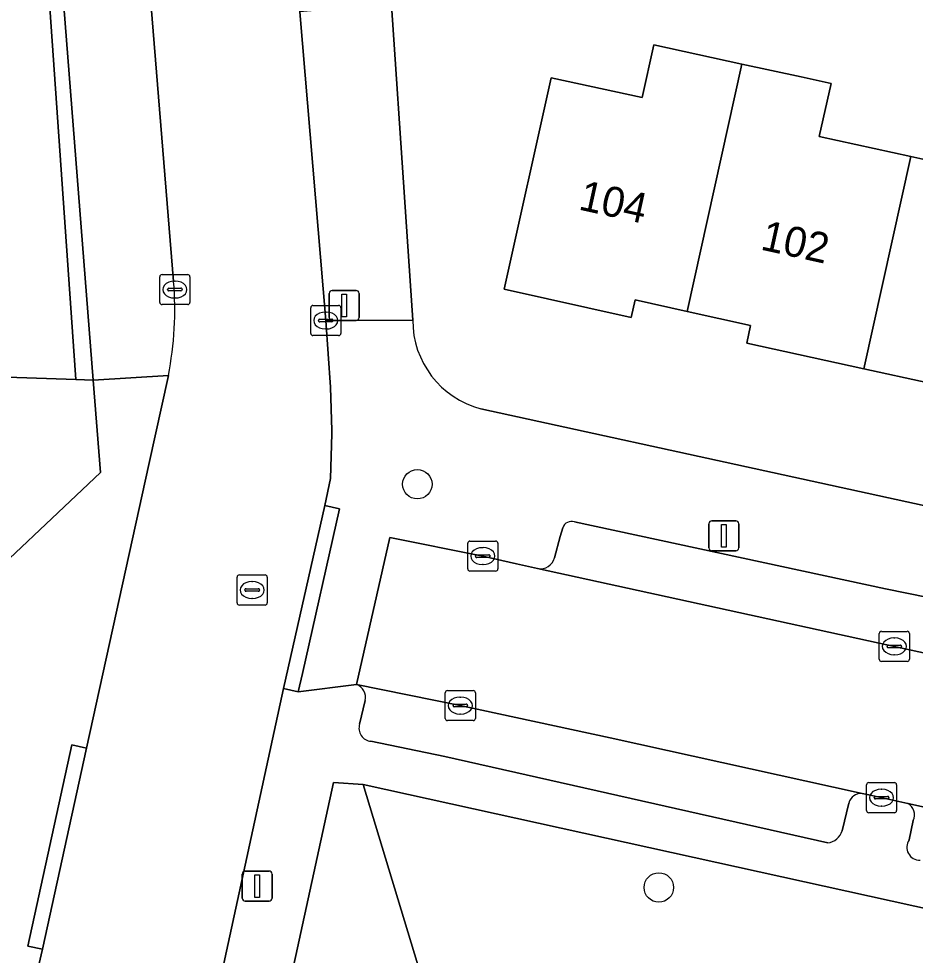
# Model space of a CAD drawing. Extents: x 162172 to 163187, y 382874 to 383685.
# Drawn here: x 162715.37 to 162745.12, y 383152.09 to 383183.19 of the extents above; entities that cross this region are included whole.
import ezdxf

# ---------------------------------------------------------------- set-up
doc = ezdxf.new("R2010")
doc.units = 0
for name, color, linetype in [('IMGEO_Berm_groen', 7, 'Continuous'), ('IMGEO_Boom', 7, 'Continuous'), ('IMGEO_Erf', 7, 'Continuous'), ('IMGEO_Groenvoorziening', 7, 'Continuous'), ('IMGEO_Haag', 7, 'Continuous'), ('IMGEO_Kolk', 7, 'Continuous'), ('IMGEO_Lichtmast', 7, 'Continuous'), ('IMGEO_Pand', 7, 'Continuous'), ('IMGEO_Pand_nummerreeks', 7, 'Continuous'), ('IMGEO_Parkeervlak_open', 7, 'Continuous'), ('IMGEO_Rijbaan_lokaal_open', 7, 'Continuous'), ('IMGEO_Rioolput', 7, 'Continuous'), ('IMGEO_Voetpad_open', 7, 'Continuous')]:
    doc.layers.add(name, color=color, linetype=linetype)

msp = doc.modelspace()

# ---------------------------------------------------------------- linework, layer by layer
at = {"layer": 'IMGEO_Berm_groen'}
msp.add_lwpolyline([(162716.279, 383185.309), (162716.729, 383185.316), (162716.471, 383188.924), (162712.883, 383188.659), (162714.318, 383171.307), (162717.264, 383171.207)], close=True, dxfattribs=at)
at = {"layer": 'IMGEO_Boom'}
for centre in [(162728.595, 383167.73), (162736.61, 383154.34)]:
    msp.add_circle(centre, 0.489, dxfattribs=at)
at = {"layer": 'IMGEO_Erf'}
for points in [[(162747.483, 383189.117), (162743.559, 383188.807), (162742.906, 383183.964), (162740.016, 383184.611), (162737.106, 383185.262), (162737.819, 383188.434), (162727.457, 383187.732), (162728.442, 383173.18)], [(162747.689, 383170.632), (162743.416, 383171.565), (162739.53, 383172.414), (162739.658, 383173), (162737.556, 383173.471), (162735.826, 383173.858), (162735.696, 383173.272), (162731.475, 383174.203), (162733.033, 383181.229), (162736.055, 383180.57), (162736.449, 383182.328)], [(162736.449, 383182.328), (162739.37, 383181.686), (162741.333, 383181.255), (162742.329, 383181.036), (162741.936, 383179.278), (162744.972, 383178.611), (162748.06, 383177.932)], [(162730.7, 383170.234), (162770.835, 383161.462)]]:
    msp.add_lwpolyline(points, dxfattribs=at)
msp.add_arc((162731.489, 383173.177), 3.047, 179.9441, 254.9936, dxfattribs=at)
at = {"layer": 'IMGEO_Groenvoorziening'}
for points in [[(162716.729, 383185.316), (162716.279, 383185.309), (162717.264, 383171.207), (162717.838, 383171.191)], [(162717.838, 383171.191), (162717.264, 383171.207), (162714.318, 383171.307), (162699.343, 383174.603), (162699.21, 383174.01), (162688.833, 383176.346), (162687.285, 383169.49), (162713.429, 383163.736), (162718.079, 383168.119)], [(162729.541, 383148.699), (162726.801, 383157.757), (162725.818, 383157.824), (162723.293, 383146.233), (162728.727, 383145.028)], [(162758.721, 383142.201), (162760.411, 383150.342), (162726.801, 383157.757), (162729.541, 383148.699), (162757.134, 383142.554)]]:
    msp.add_lwpolyline(points, close=True, dxfattribs=at)
at = {"layer": 'IMGEO_Haag'}
msp.add_lwpolyline([(162699.343, 383174.603), (162699.21, 383174.01), (162688.833, 383176.346), (162687.285, 383169.49), (162713.429, 383163.736), (162718.079, 383168.119), (162717.838, 383171.191), (162717.264, 383171.207), (162714.318, 383171.307)], close=True, dxfattribs=at)
at = {"layer": 'IMGEO_Kolk'}
for p, q in [((162720.123, 383174.695), (162720.975, 383174.695)), ((162720.048, 383173.769), (162720.048, 383174.621)), ((162720.536, 383174.475), (162720.561, 383174.475)), ((162721.049, 383174.621), (162721.049, 383173.769)), ((162720.307, 383174.189), (162720.307, 383174.201)), ((162720.745, 383174.152), (162720.347, 383174.152)), ((162720.35, 383174.238), (162720.748, 383174.238)), ((162720.791, 383174.201), (162720.791, 383174.189)), ((162720.559, 383173.915), (162720.534, 383173.915)), ((162720.975, 383173.695), (162720.123, 383173.695)), ((162725.057, 383172.741), (162725.057, 383173.593)), ((162725.132, 383173.667), (162725.984, 383173.667)), ((162725.545, 383173.447), (162725.57, 383173.447)), ((162726.058, 383173.593), (162726.058, 383172.741)), ((162725.316, 383173.161), (162725.316, 383173.173)), ((162725.754, 383173.124), (162725.356, 383173.124)), ((162725.359, 383173.21), (162725.757, 383173.21)), ((162725.8, 383173.173), (162725.8, 383173.161)), ((162725.568, 383172.887), (162725.543, 383172.887)), ((162725.984, 383172.667), (162725.132, 383172.667)), ((162730.268, 383164.918), (162730.268, 383165.77)), ((162730.343, 383165.844), (162731.195, 383165.844)), ((162731.269, 383165.77), (162731.269, 383164.918)), ((162730.527, 383165.338), (162730.527, 383165.35)), ((162730.57, 383165.387), (162730.968, 383165.387)), ((162730.756, 383165.624), (162730.781, 383165.624)), ((162731.011, 383165.35), (162731.011, 383165.338)), ((162730.965, 383165.301), (162730.567, 383165.301)), ((162730.779, 383165.064), (162730.754, 383165.064)), ((162731.195, 383164.844), (162730.343, 383164.844)), ((162744.002, 383162.845), (162744.854, 383162.845)), ((162743.927, 383161.919), (162743.927, 383162.771)), ((162744.415, 383162.625), (162744.44, 383162.625)), ((162744.928, 383162.771), (162744.928, 383161.919)), ((162744.186, 383162.339), (162744.186, 383162.351)), ((162744.624, 383162.302), (162744.226, 383162.302)), ((162744.229, 383162.388), (162744.627, 383162.388)), ((162744.67, 383162.351), (162744.67, 383162.339)), ((162744.438, 383162.065), (162744.413, 383162.065)), ((162744.854, 383161.845), (162744.002, 383161.845)), ((162729.522, 383159.953), (162729.522, 383160.805)), ((162729.597, 383160.879), (162730.449, 383160.879)), ((162730.523, 383160.805), (162730.523, 383159.953)), ((162729.781, 383160.373), (162729.781, 383160.385)), ((162729.824, 383160.422), (162730.222, 383160.422)), ((162730.01, 383160.659), (162730.035, 383160.659)), ((162730.265, 383160.385), (162730.265, 383160.373)), ((162730.219, 383160.336), (162729.821, 383160.336)), ((162730.033, 383160.099), (162730.008, 383160.099)), ((162730.449, 383159.879), (162729.597, 383159.879)), ((162743.503, 383156.895), (162743.503, 383157.747)), ((162743.578, 383157.821), (162744.43, 383157.821)), ((162743.991, 383157.601), (162744.016, 383157.601)), ((162744.504, 383157.747), (162744.504, 383156.895)), ((162743.762, 383157.315), (162743.762, 383157.327)), ((162744.2, 383157.278), (162743.802, 383157.278)), ((162743.805, 383157.364), (162744.203, 383157.364)), ((162744.246, 383157.327), (162744.246, 383157.315)), ((162744.014, 383157.041), (162743.989, 383157.041)), ((162744.43, 383156.821), (162743.578, 383156.821))]:
    msp.add_line(p, q, dxfattribs=at)
for points in [[(162720.123, 383174.695), (162720.975, 383174.695)], [(162720.048, 383173.769), (162720.048, 383174.621)], [(162721.049, 383174.621), (162721.049, 383173.769)], [(162720.975, 383173.695), (162720.123, 383173.695)], [(162725.057, 383172.741), (162725.057, 383173.593)], [(162725.132, 383173.667), (162725.984, 383173.667)], [(162726.058, 383173.593), (162726.058, 383172.741)], [(162725.984, 383172.667), (162725.132, 383172.667)], [(162730.268, 383164.918), (162730.268, 383165.77)], [(162730.343, 383165.844), (162731.195, 383165.844)], [(162731.269, 383165.77), (162731.269, 383164.918)], [(162731.195, 383164.844), (162730.343, 383164.844)], [(162744.002, 383162.845), (162744.854, 383162.845)], [(162743.927, 383161.919), (162743.927, 383162.771)], [(162744.928, 383162.771), (162744.928, 383161.919)], [(162744.854, 383161.845), (162744.002, 383161.845)], [(162729.522, 383159.953), (162729.522, 383160.805)], [(162729.597, 383160.879), (162730.449, 383160.879)], [(162730.523, 383160.805), (162730.523, 383159.953)], [(162730.449, 383159.879), (162729.597, 383159.879)], [(162743.503, 383156.895), (162743.503, 383157.747)], [(162743.578, 383157.821), (162744.43, 383157.821)], [(162744.504, 383157.747), (162744.504, 383156.895)], [(162744.43, 383156.821), (162743.578, 383156.821)]]:
    msp.add_lwpolyline(points, dxfattribs=at)
for centre, radius, start, end in [((162720.125, 383174.619), 0.0765, 91.552, 178.448), ((162720.125, 383174.619), 0.0765, 91.552, 178.448), ((162720.973, 383174.619), 0.0765, 1.552, 88.448), ((162720.973, 383174.619), 0.0765, 1.552, 88.448), ((162720.347, 383174.198), 0.0403, 85.8775, 175.7526), ((162720.344, 383174.188), 0.0366, 178.938, 274.7102), ((162720.748, 383174.195), 0.043, 264.8664, 352.4533), ((162720.752, 383174.2), 0.0386, 1.7309, 96.639), ((162720.125, 383173.771), 0.0765, 181.552, 268.448), ((162720.125, 383173.771), 0.0765, 181.552, 268.448), ((162720.973, 383173.771), 0.0765, 271.552, 358.448), ((162720.973, 383173.771), 0.0765, 271.552, 358.448), ((162725.134, 383173.591), 0.0765, 91.552, 178.448), ((162725.134, 383173.591), 0.0765, 91.552, 178.448), ((162725.982, 383173.591), 0.0765, 1.552, 88.448), ((162725.982, 383173.591), 0.0765, 1.552, 88.448), ((162725.356, 383173.17), 0.0403, 85.8775, 175.7526), ((162725.353, 383173.16), 0.0366, 178.938, 274.7102), ((162725.757, 383173.167), 0.043, 264.8664, 352.4533), ((162725.761, 383173.172), 0.0386, 1.7309, 96.639), ((162725.134, 383172.743), 0.0765, 181.552, 268.448), ((162725.134, 383172.743), 0.0765, 181.552, 268.448), ((162725.982, 383172.743), 0.0765, 271.552, 358.448), ((162725.982, 383172.743), 0.0765, 271.552, 358.448), ((162730.345, 383165.768), 0.0765, 91.552, 178.448), ((162730.345, 383165.768), 0.0765, 91.552, 178.448), ((162731.193, 383165.768), 0.0765, 1.552, 88.448), ((162731.193, 383165.768), 0.0765, 1.552, 88.448), ((162730.567, 383165.347), 0.0403, 85.8775, 175.7526), ((162730.564, 383165.337), 0.0366, 178.938, 274.7102), ((162730.968, 383165.344), 0.043, 264.8664, 352.4533), ((162730.972, 383165.349), 0.0386, 1.7309, 96.639), ((162730.345, 383164.92), 0.0765, 181.552, 268.448), ((162730.345, 383164.92), 0.0765, 181.552, 268.448), ((162731.193, 383164.92), 0.0765, 271.552, 358.448), ((162731.193, 383164.92), 0.0765, 271.552, 358.448), ((162744.004, 383162.769), 0.0765, 91.552, 178.448), ((162744.004, 383162.769), 0.0765, 91.552, 178.448), ((162744.852, 383162.769), 0.0765, 1.552, 88.448), ((162744.852, 383162.769), 0.0765, 1.552, 88.448), ((162744.226, 383162.348), 0.0403, 85.8775, 175.7526), ((162744.223, 383162.338), 0.0366, 178.938, 274.7102), ((162744.627, 383162.345), 0.043, 264.8664, 352.4533), ((162744.631, 383162.35), 0.0386, 1.7309, 96.639), ((162744.004, 383161.921), 0.0765, 181.552, 268.448), ((162744.004, 383161.921), 0.0765, 181.552, 268.448), ((162744.852, 383161.921), 0.0765, 271.552, 358.448), ((162744.852, 383161.921), 0.0765, 271.552, 358.448), ((162729.599, 383160.803), 0.0765, 91.552, 178.448), ((162729.599, 383160.803), 0.0765, 91.552, 178.448), ((162730.447, 383160.803), 0.0765, 1.552, 88.448), ((162730.447, 383160.803), 0.0765, 1.552, 88.448), ((162729.821, 383160.382), 0.0403, 85.8775, 175.7526), ((162729.818, 383160.372), 0.0366, 178.938, 274.7102), ((162730.222, 383160.379), 0.043, 264.8664, 352.4533), ((162730.226, 383160.384), 0.0386, 1.7309, 96.639), ((162729.599, 383159.955), 0.0765, 181.552, 268.448), ((162729.599, 383159.955), 0.0765, 181.552, 268.448), ((162730.447, 383159.955), 0.0765, 271.552, 358.448), ((162730.447, 383159.955), 0.0765, 271.552, 358.448), ((162743.58, 383157.745), 0.0765, 91.552, 178.448), ((162743.58, 383157.745), 0.0765, 91.552, 178.448), ((162744.428, 383157.745), 0.0765, 1.552, 88.448), ((162744.428, 383157.745), 0.0765, 1.552, 88.448), ((162743.802, 383157.324), 0.0403, 85.8775, 175.7526), ((162743.799, 383157.314), 0.0366, 178.938, 274.7102), ((162744.203, 383157.321), 0.043, 264.8664, 352.4533), ((162744.207, 383157.326), 0.0386, 1.7309, 96.639), ((162743.58, 383156.897), 0.0765, 181.552, 268.448), ((162743.58, 383156.897), 0.0765, 181.552, 268.448), ((162744.428, 383156.897), 0.0765, 271.552, 358.448), ((162744.428, 383156.897), 0.0765, 271.552, 358.448)]:
    msp.add_arc(centre, radius, start, end, dxfattribs=at)
for centre, major_axis, ratio, start_param, end_param in [((162720.535, 383174.195), (-0.387, 0.002), 0.722429, 4.712389, 7.853982), ((162720.56, 383174.195), (-0.39, 0.002), 0.717154, 1.570796, 4.712389), ((162725.544, 383173.167), (-0.387, 0.002), 0.722429, 4.712389, 7.853982), ((162725.569, 383173.167), (-0.39, 0.002), 0.717154, 1.570796, 4.712389), ((162730.755, 383165.344), (-0.387, 0.002), 0.722429, 4.712389, 7.853982), ((162730.78, 383165.344), (-0.39, 0.002), 0.717154, 1.570796, 4.712389), ((162744.414, 383162.345), (-0.387, 0.002), 0.722429, 4.712389, 7.853982), ((162744.439, 383162.345), (-0.39, 0.002), 0.717154, 1.570796, 4.712389), ((162730.009, 383160.379), (-0.387, 0.002), 0.722429, 4.712389, 7.853982), ((162730.034, 383160.379), (-0.39, 0.002), 0.717154, 1.570796, 4.712389), ((162743.99, 383157.321), (-0.387, 0.002), 0.722429, 4.712389, 7.853982), ((162744.015, 383157.321), (-0.39, 0.002), 0.717154, 1.570796, 4.712389)]:
    msp.add_ellipse(centre, major_axis=major_axis, ratio=ratio, start_param=start_param, end_param=end_param, dxfattribs=at)
at = {"layer": 'IMGEO_Lichtmast'}
for p, q in [((162725.672, 383173.266), (162725.672, 383174.066)), ((162725.672, 383174.066), (162725.672, 383173.266)), ((162725.772, 383174.166), (162726.562, 383174.166)), ((162726.562, 383174.166), (162725.772, 383174.166)), ((162726.662, 383174.066), (162726.662, 383173.266)), ((162726.662, 383173.266), (162726.662, 383174.066)), ((162726.562, 383173.166), (162725.772, 383173.166)), ((162725.772, 383173.166), (162726.562, 383173.166)), ((162738.272, 383165.617), (162738.272, 383166.417)), ((162738.272, 383166.417), (162738.272, 383165.617)), ((162738.372, 383166.517), (162739.162, 383166.517)), ((162739.162, 383166.517), (162738.372, 383166.517)), ((162739.262, 383166.417), (162739.262, 383165.617)), ((162739.262, 383165.617), (162739.262, 383166.417)), ((162739.162, 383165.517), (162738.372, 383165.517)), ((162738.372, 383165.517), (162739.162, 383165.517)), ((162722.783, 383153.984), (162722.783, 383154.784)), ((162722.783, 383154.784), (162722.783, 383153.984)), ((162722.883, 383154.884), (162723.673, 383154.884)), ((162723.673, 383154.884), (162722.883, 383154.884)), ((162723.773, 383154.784), (162723.773, 383153.984)), ((162723.773, 383153.984), (162723.773, 383154.784)), ((162723.673, 383153.884), (162722.883, 383153.884)), ((162722.883, 383153.884), (162723.673, 383153.884))]:
    msp.add_line(p, q, dxfattribs=at)
for points in [[(162726.092, 383174.041), (162726.242, 383174.041), (162726.242, 383173.291), (162726.092, 383173.291), (162726.092, 383174.041)], [(162738.692, 383166.392), (162738.842, 383166.392), (162738.842, 383165.642), (162738.692, 383165.642), (162738.692, 383166.392)], [(162723.203, 383154.759), (162723.353, 383154.759), (162723.353, 383154.009), (162723.203, 383154.009), (162723.203, 383154.759)]]:
    msp.add_lwpolyline(points, dxfattribs=at)
for centre, start, end in [((162725.772, 383174.066), 90, 180), ((162725.772, 383174.066), 90, 180), ((162726.562, 383174.066), 0, 90), ((162726.562, 383174.066), 360, 90), ((162725.772, 383173.266), 180, 270), ((162725.772, 383173.266), 180, 270), ((162726.562, 383173.266), 270, 0), ((162726.562, 383173.266), 270, 0), ((162738.372, 383166.417), 90, 180), ((162738.372, 383166.417), 90, 180), ((162739.162, 383166.417), 0, 90), ((162739.162, 383166.417), 360, 90), ((162738.372, 383165.617), 180, 270), ((162738.372, 383165.617), 180, 270), ((162739.162, 383165.617), 270, 0), ((162739.162, 383165.617), 270, 0), ((162722.883, 383154.784), 90, 180), ((162722.883, 383154.784), 90, 180), ((162723.673, 383154.784), 0, 90), ((162723.673, 383154.784), 360, 90), ((162722.883, 383153.984), 180, 270), ((162722.883, 383153.984), 180, 270), ((162723.673, 383153.984), 270, 0), ((162723.673, 383153.984), 270, 0)]:
    msp.add_arc(centre, 0.1, start, end, dxfattribs=at)
at = {"layer": 'IMGEO_Pand'}
for points in [[(162739.37, 383181.686), (162736.449, 383182.328), (162736.055, 383180.57), (162733.033, 383181.229), (162731.475, 383174.203), (162735.696, 383173.272), (162735.826, 383173.858), (162737.556, 383173.471)], [(162739.37, 383181.686), (162737.556, 383173.471), (162739.658, 383173), (162739.53, 383172.414), (162743.416, 383171.565), (162744.972, 383178.611), (162741.936, 383179.278), (162742.329, 383181.036), (162741.333, 383181.255)], [(162749.536, 383170.842), (162751.349, 383179.054), (162748.454, 383179.69), (162748.06, 383177.932), (162744.972, 383178.611), (162743.416, 383171.565), (162747.689, 383170.632), (162747.817, 383171.218)]]:
    msp.add_lwpolyline(points, close=True, dxfattribs=at)
at = {"layer": 'IMGEO_Parkeervlak_open'}
for points in [[(162733.421, 383166.283), (162733.34, 383165.995), (162733.15, 383165.288)], [(162749.197, 383163.223), (162744.13, 383164.261), (162733.812, 383166.484)], [(162732.589, 383164.93), (162749.898, 383161.148)], [(162735, 383159.308), (162730.017, 383160.386), (162726.58, 383161.079)], [(162726.863, 383160.546), (162726.68, 383159.761)], [(162727.057, 383159.194), (162729.503, 383158.69), (162742.216, 383155.818)], [(162743.362, 383157.464), (162735, 383159.308)], [(162742.698, 383156.225), (162742.916, 383157.14)], [(162761.601, 383153.44), (162744.873, 383157.13)], [(162745.056, 383156.561), (162744.917, 383155.917)]]:
    msp.add_lwpolyline(points, dxfattribs=at)
for centre, radius, start, end in [((162733.717, 383166.187), 0.312, 72.3271, 162.0852), ((162732.674, 383165.416), 0.493, 260.0817, 345.0059), ((162726.431, 383160.658), 0.446, 345.4327, 70.5001), ((162727.092, 383159.626), 0.433, 161.861, 265.3791), ((162743.336, 383157.031), 0.434, 86.5336, 165.46), ((162744.665, 383156.749), 0.434, 334.3304, 61.3269), ((162742.142, 383156.395), 0.582, 277.348, 343.0074), ((162745.265, 383155.673), 0.425, 144.9816, 272.719)]:
    msp.add_arc(centre, radius, start, end, dxfattribs=at)
at = {"layer": 'IMGEO_Rijbaan_lokaal_open'}
for points in [[(162716.618, 383222.588), (162717.135, 383219.11), (162717.258, 383217.338), (162717.931, 383208.143), (162718.659, 383196.919), (162718.681, 383196.574), (162718.735, 383196.282), (162720.508, 383174.468)], [(162720.332, 383171.339), (162719.685, 383168.388), (162717.621, 383158.967), (162716.16, 383152.285), (162715.139, 383147.923), (162721.042, 383146.61), (162724.159, 383160.942), (162725.521, 383167.025), (162725.709, 383167.926), (162725.753, 383169.405), (162725.756, 383169.512), (162725.711, 383170.959), (162725.556, 383173.167), (162724.694, 383183.415), (162724.622, 383184.384), (162724.379, 383187.917), (162723.663, 383198.352), (162721.935, 383221.945)]]:
    msp.add_lwpolyline(points, dxfattribs=at)
msp.add_lwpolyline([(162750.77, 383160.957), (162750.653, 383160.983), (162749.898, 383161.148), (162732.589, 383164.93), (162731.885, 383165.083), (162730.774, 383165.342), (162727.678, 383165.963), (162726.58, 383161.079), (162730.017, 383160.386), (162735, 383159.308), (162743.362, 383157.464), (162743.584, 383157.415), (162744.873, 383157.13), (162761.601, 383153.44), (162761.987, 383153.355), (162766.11, 383152.445), (162767.183, 383152.197), (162768.266, 383157.061), (162767.785, 383157.168), (162767.416, 383157.25)], close=True, dxfattribs=at)
msp.add_arc((162709.145, 383173.538), 11.401, 348.881, 4.6803, dxfattribs=at)
at = {"layer": 'IMGEO_Rioolput'}
for p, q in [((162722.689, 383164.718), (162723.541, 383164.718)), ((162722.614, 383163.792), (162722.614, 383164.644)), ((162723.102, 383164.498), (162723.127, 383164.498)), ((162723.615, 383164.644), (162723.615, 383163.792)), ((162722.873, 383164.212), (162722.873, 383164.224)), ((162723.311, 383164.175), (162722.913, 383164.175)), ((162722.916, 383164.261), (162723.314, 383164.261)), ((162723.357, 383164.224), (162723.357, 383164.212)), ((162723.125, 383163.938), (162723.1, 383163.938)), ((162723.541, 383163.718), (162722.689, 383163.718))]:
    msp.add_line(p, q, dxfattribs=at)
for points in [[(162722.689, 383164.718), (162723.541, 383164.718)], [(162722.614, 383163.792), (162722.614, 383164.644)], [(162723.615, 383164.644), (162723.615, 383163.792)], [(162723.541, 383163.718), (162722.689, 383163.718)]]:
    msp.add_lwpolyline(points, dxfattribs=at)
for centre, radius, start, end in [((162722.691, 383164.642), 0.0765, 91.552, 178.448), ((162722.691, 383164.642), 0.0765, 91.552, 178.448), ((162723.539, 383164.642), 0.0765, 1.552, 88.448), ((162723.539, 383164.642), 0.0765, 1.552, 88.448), ((162722.913, 383164.221), 0.0403, 85.8775, 175.7526), ((162722.91, 383164.211), 0.0366, 178.938, 274.7102), ((162723.314, 383164.218), 0.043, 264.8664, 352.4533), ((162723.318, 383164.223), 0.0386, 1.7309, 96.639), ((162722.691, 383163.794), 0.0765, 181.552, 268.448), ((162722.691, 383163.794), 0.0765, 181.552, 268.448), ((162723.539, 383163.794), 0.0765, 271.552, 358.448), ((162723.539, 383163.794), 0.0765, 271.552, 358.448)]:
    msp.add_arc(centre, radius, start, end, dxfattribs=at)
for centre, major_axis, ratio, start_param, end_param in [((162723.101, 383164.218), (-0.387, 0.002), 0.722429, 4.712389, 7.853982), ((162723.126, 383164.218), (-0.39, 0.002), 0.717154, 1.570796, 4.712389)]:
    msp.add_ellipse(centre, major_axis=major_axis, ratio=ratio, start_param=start_param, end_param=end_param, dxfattribs=at)
at = {"layer": 'IMGEO_Voetpad_open'}
for points in [[(162721.935, 383221.945), (162723.663, 383198.352), (162724.379, 383187.917), (162724.877, 383187.961), (162725.192, 383183.459), (162724.694, 383183.415), (162725.556, 383173.167), (162728.442, 383173.18), (162727.457, 383187.732), (162727.343, 383189.418), (162726.951, 383195.201), (162724.683, 383225.868)], [(162713.132, 383220.561), (162714.85, 383196.217), (162715.861, 383196.364), (162715.885, 383196.064), (162715.902, 383195.847), (162716.113, 383193.154), (162716.13, 383192.941), (162716.347, 383190.18), (162716.396, 383189.971), (162716.471, 383188.924), (162716.729, 383185.316), (162717.838, 383171.191), (162720.332, 383171.339)], [(162720.508, 383174.468), (162718.735, 383196.282)], [(162709.068, 383146.272), (162712.48, 383145.52), (162712.586, 383146.008), (162721.871, 383143.974), (162721.042, 383146.61), (162715.139, 383147.923), (162716.16, 383152.285), (162715.672, 383152.391), (162717.133, 383159.073), (162717.621, 383158.967), (162719.685, 383168.388), (162720.332, 383171.339), (162717.838, 383171.191), (162718.079, 383168.119), (162713.429, 383163.736), (162687.285, 383169.49), (162683.655, 383170.289), (162664.103, 383174.592), (162663.985, 383174.166), (162678.544, 383170.958)], [(162728.442, 383173.18), (162725.556, 383173.167), (162725.711, 383170.959), (162725.756, 383169.512), (162725.753, 383169.405), (162725.709, 383167.926), (162725.521, 383167.025), (162726.008, 383166.916), (162724.782, 383161.441), (162724.646, 383160.833), (162726.58, 383161.079), (162727.678, 383165.963), (162730.774, 383165.342), (162731.885, 383165.083), (162732.589, 383164.93)], [(162789.447, 383157.378), (162788.951, 383157.514), (162788.468, 383157.647), (162780.272, 383159.338), (162776.756, 383160.123), (162772.85, 383161.022), (162770.835, 383161.462), (162730.7, 383170.234)], [(162733.15, 383165.288), (162733.34, 383165.995), (162733.421, 383166.283)], [(162733.812, 383166.484), (162744.13, 383164.261), (162749.197, 383163.223)], [(162726.58, 383161.079), (162724.646, 383160.833), (162724.159, 383160.942), (162721.042, 383146.61), (162723.293, 383146.233), (162725.818, 383157.824), (162726.801, 383157.757), (162760.411, 383150.342), (162768.657, 383148.523), (162769.31, 383148.379)], [(162726.68, 383159.761), (162726.863, 383160.546)], [(162742.216, 383155.818), (162729.503, 383158.69), (162727.057, 383159.194)], [(162744.873, 383157.13), (162743.584, 383157.415), (162743.362, 383157.464)], [(162742.916, 383157.14), (162742.698, 383156.225)], [(162744.917, 383155.917), (162745.056, 383156.561)]]:
    msp.add_lwpolyline(points, dxfattribs=at)
for points in [[(162724.159, 383160.942), (162724.646, 383160.833), (162724.782, 383161.441), (162726.008, 383166.916), (162725.521, 383167.025)], [(162716.16, 383152.285), (162717.621, 383158.967), (162717.133, 383159.073), (162715.672, 383152.391)]]:
    msp.add_lwpolyline(points, close=True, dxfattribs=at)
for centre, radius, start, end in [((162709.145, 383173.538), 11.401, 348.881, 4.6803), ((162731.489, 383173.177), 3.047, 179.9441, 254.9936), ((162733.717, 383166.187), 0.312, 72.3271, 162.0852), ((162732.674, 383165.416), 0.493, 260.0817, 345.0059), ((162726.431, 383160.658), 0.446, 345.4327, 70.5001), ((162727.092, 383159.626), 0.433, 161.861, 265.3791), ((162743.336, 383157.031), 0.434, 86.5336, 165.46), ((162744.665, 383156.749), 0.434, 334.3304, 61.3269), ((162742.142, 383156.395), 0.582, 277.348, 343.0074), ((162745.265, 383155.673), 0.425, 144.9816, 272.719)]:
    msp.add_arc(centre, radius, start, end, dxfattribs=at)

# ---------------------------------------------------------------- texts
at = {"layer": 'IMGEO_Pand_nummerreeks'}
for s, p in [('104', (162733.912, 383176.86)), ('102', (162739.953, 383175.53))]:
    msp.add_text(s, height=1, rotation=347.5747, dxfattribs=at).set_placement(p)

doc.saveas('drawing.dxf')
